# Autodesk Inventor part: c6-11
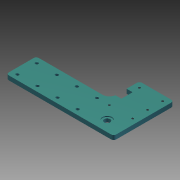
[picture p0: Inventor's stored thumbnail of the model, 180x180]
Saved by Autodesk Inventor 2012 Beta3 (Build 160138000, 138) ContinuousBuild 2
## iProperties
Created: 2010-12
Part Number: c6-11
Material: Steel
Document SubType Name: Modeling
Designer: Beta-8540w
Mass: 1769.34 g
Surface Area: 558.866 cm^2
Volume: 225.394 cm^3
Density: 7.85 g/cm^3
Author: Beta-8540w
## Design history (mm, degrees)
sketch "Sketch1"
  geometry: L1 (0, 0)-(250, 0); L2 (250, 0)-(250, 70); L3 (250, 70)-(0, 70); L4 (0, 70)-(0, 0); L5 (250, 70)-(170, 70); L6 (170, 70)-(170, 140); L7 (170, 140)-(250, 140); L8 (250, 140)-(250, 70)
  constraints: 16 end point, 4 parallel, 2 horizontal, 2 perpendicular
  dimensions: "d0" = 250 distance of L3.end L2.end; "d1" = 70 distance of L2.end L1.end; "d2" = 80 distance of L6.end L7.end; "d3" = 70 distance of L5.end L6.end
extrude "Extrusion1" new body sketch "Sketch1" distance "d4" = 10; taper "d5" = 0 deg
sketch "Sketch4"
  geometry: L1 (250, 140)-(170, 140) reference; L2 (170, 140)-(170, 70) reference; L3 (170, 84)-(184, 84); L4 (184, 84)-(184, 110); L5 (184, 110)-(170, 110); L6 (170, 110)-(170, 84)
  constraints: 8 end point, 2 parallel, 1 horizontal, 1 perpendicular, 1 point on line
  dimensions: "d41" = 14 distance of L5.end L4.end; "d42" = 26 distance of L4.end L3.end; "d43" = 30 distance between parallel lines of L1 L5
extrude "Extrusion2" cut sketch "Sketch4" stored distance "d44" = 10; taper "d45" = 0 deg
sketch "Sketch2"
  geometry: L1 (0, 70)-(0, 0) reference; L2 (14, 12.5)-(154, 12.5); L3 (154, 12.5)-(154, 57.5); L4 (154, 57.5)-(14, 57.5); L5 (14, 57.5)-(14, 12.5); L6 (60.667, 57.5)-(60.667, 12.5); L7 (107.333, 57.5)-(107.333, 12.5); 2 further points
  constraints: 12 end point, 4 point on line, 3 perpendicular, 2 midpoint, 2 parallel, 1 horizontal, 1 horizontal alignment
  dimensions: "d6" = 140 distance of L4.end L3.end; "d7" = 45 distance of L3.end L2.end; "d8" = 46.66667 distance between parallel lines of L6 L5 (= 0.333333 x d6); "d9" = 46.66667 distance between parallel lines of L7 L6 (= d8); "d10" = 14 distance between parallel lines of L1 L5
hole "Hole1" sketch "Sketch2" at (14, 12.5), (154, 57.5), (154, 12.5), (14, 57.5), (60.667, 57.5), (60.667, 12.5), (107.333, 57.5), (107.333, 12.5) diameter "d11" = 6.6; stored, may be unused: countersink angle "d15" = 90 deg, drill point angle "d17" = 118 deg; dims "d12" = 6, "d13" = 4, "d14" = 90, "d16" = 8
sketch "Sketch3"
  geometry: L1 (250, 0)-(250, 140) reference; L2 (250, 140)-(170, 140) reference; L3 (170, 140)-(170, 70) reference; L4 (0, 0)-(250, 0) reference; L5 (183, 127)-(237, 127); L6 (237, 127)-(237, 92); L7 (237, 92)-(237, 57); L8 (237, 57)-(183, 57)
  constraints: 8 end point, 2 equal length, 2 parallel, 1 collinear, 1 perpendicular
  dimensions: "d18" = 13 distance between parallel lines of L1 L6; "d19" = 13 distance from line of L3 L5.start (= d18); "d20" = 13 distance between parallel lines of L2 L5 (= d18); "d22" = 35 distance of L6.end L7.end
hole "Hole2" sketch "Sketch3" at (183, 127), (237, 127), (237, 92), (237, 57), (183, 57) diameter "d23" = 4.917; stored, may be unused: countersink angle "d27" = 90 deg, drill point angle "d29" = 118 deg; dims "d24" = 6, "d25" = 4, "d26" = 90, "d28" = 8
hole "Hole3" diameter "d32" = 13.492; stored, may be unused: countersink angle "d36" = 90 deg, drill point angle "d38" = 118 deg; dims "d30" = 40, "d31" = 25, "d33" = 6, "d34" = 22.225, "d35" = 2, "d37" = 8
fillet "Fillet1" dims "d39" = 6, "d46" = 1
fillet "Fillet2" dims "d40" = 16
chamfer "Chamfer1" distance "d47" = 0.5; stored, may be unused: second distance "d48" = 2, angle "d49" = 45 deg
hole "Hole4" diameter "d52" = 3.242; stored, may be unused: countersink angle "d56" = 90 deg, drill point angle "d58" = 118 deg; dims "d50" = 43, "d51" = 5, "d53" = 8, "d54" = 4, "d55" = 2, "d57" = 10
chamfer "Chamfer2" distance "d59" = 0.5; stored, may be unused: second distance "d60" = 2, angle "d61" = 45 deg
body "Solid1"
